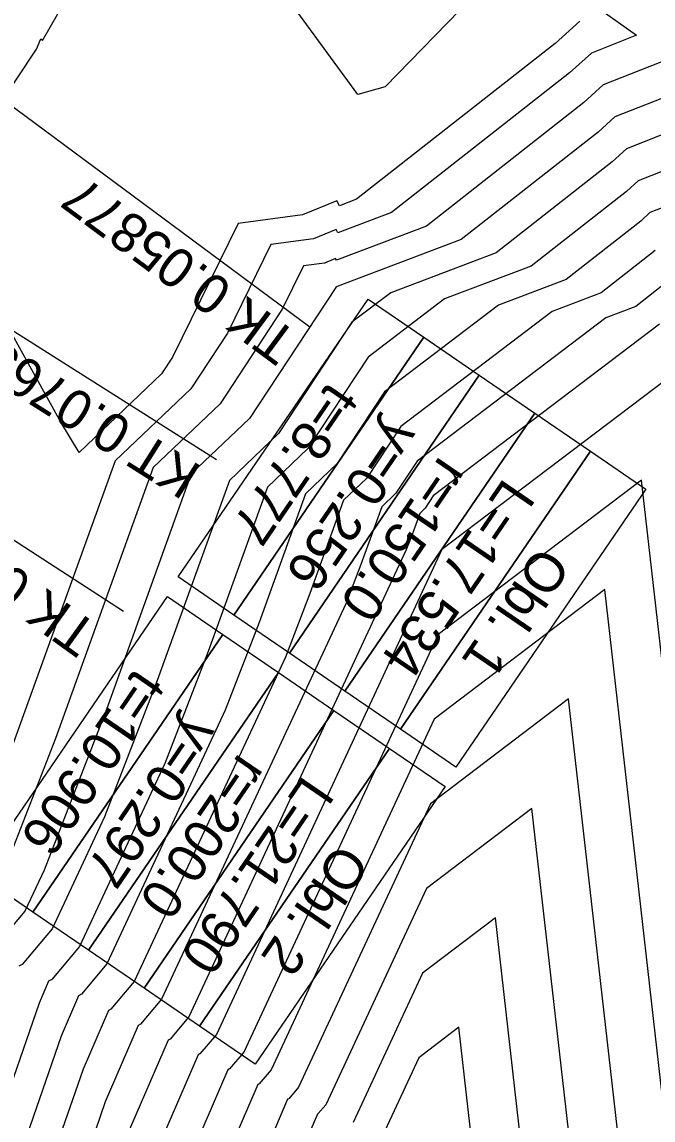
# Model space of a CAD drawing. Extents: x -549394 to -546608, y -1037055 to -1033629.
# Drawn here: x -547683.6 to -547627.3, y -1035531 to -1035433.2 of the extents above; entities that cross this region are included whole.
import ezdxf

# ---------------------------------------------------------------- set-up
doc = ezdxf.new("R2010")
doc.units = 0
for name, color, linetype in [('hlavni_vrst', 7, 'Continuous'), ('norm_vrst', 7, 'Continuous'), ('x_popis_oblouky_C11', 7, 'Continuous')]:
    doc.layers.add(name, color=color, linetype=linetype)

msp = doc.modelspace()

# ---------------------------------------------------------------- linework, layer by layer
at = {"layer": 'hlavni_vrst'}
for p, q in [((-547681.724, -1035434.805), (-547680.351, -1035432.432)), ((-547633.807, -1035433.081), (-547635.991, -1035435.065)), ((-547682.267, -1035435.588), (-547681.864, -1035434.669)), ((-547681.864, -1035434.669), (-547681.724, -1035434.805)), ((-547689.504, -1035446.371), (-547682.267, -1035435.588)), ((-547635.991, -1035435.065), (-547653.716, -1035448.961)), ((-547609.481, -1035439.742), (-547628.59, -1035447.31)), ((-547628.59, -1035447.31), (-547629.638, -1035448.262)), ((-547629.638, -1035448.262), (-547638.141, -1035454.928)), ((-547655.485, -1035449.097), (-547658.547, -1035450.343)), ((-547655.242, -1035449.539), (-547655.485, -1035449.097)), ((-547653.716, -1035448.961), (-547655.242, -1035449.539)), ((-547658.547, -1035450.343), (-547664.284, -1035451.115)), ((-547664.284, -1035451.115), (-547670.133, -1035463.032)), ((-547680.08, -1035468.83), (-547689.44, -1035452.019)), ((-547638.141, -1035454.928), (-547645.859, -1035457.851)), ((-547645.859, -1035457.851), (-547652.671, -1035463.026)), ((-547670.133, -1035463.032), (-547671.116, -1035464.522)), ((-547652.671, -1035463.026), (-547658.046, -1035471.179)), ((-547671.116, -1035464.522), (-547678.465, -1035471.524)), ((-547625.05, -1035464.235), (-547646.101, -1035480.198)), ((-547678.465, -1035471.524), (-547680.08, -1035468.83)), ((-547658.046, -1035471.179), (-547661.662, -1035474.623)), ((-547661.662, -1035474.623), (-547666.946, -1035489.268)), ((-547646.101, -1035480.198), (-547666.218, -1035523.415)), ((-547666.946, -1035489.268), (-547670.822, -1035499.262)), ((-547670.822, -1035499.262), (-547678.409, -1035515.562)), ((-547641.329, -1035513.014), (-547647.822, -1035517.938)), ((-547638.603, -1035537.022), (-547641.329, -1035513.014)), ((-547678.409, -1035515.562), (-547680.899, -1035518.502)), ((-547647.822, -1035517.938), (-547654.027, -1035531.268)), ((-547681.173, -1035518.651), (-547682.031, -1035520.636)), ((-547680.899, -1035518.502), (-547681.173, -1035518.651)), ((-547682.031, -1035520.636), (-547685.776, -1035531.456)), ((-547666.218, -1035523.415), (-547667.69, -1035525.153)), ((-547667.852, -1035525.241), (-547672.195, -1035535.297)), ((-547667.69, -1035525.153), (-547667.852, -1035525.241))]:
    msp.add_line(p, q, dxfattribs=at)
at = {"layer": 'norm_vrst'}
for p, q in [((-547653.591, -1035439.61), (-547662.004, -1035428.111)), ((-547641.292, -1035428.807), (-547651.172, -1035438.937)), ((-547632.01, -1035432.002), (-547628.761, -1035434.341)), ((-547628.761, -1035434.341), (-547632.764, -1035435.927)), ((-547623.941, -1035435.692), (-547631.721, -1035438.773)), ((-547632.764, -1035435.927), (-547634.72, -1035437.704)), ((-547634.72, -1035437.704), (-547650.601, -1035450.154)), ((-547619.121, -1035437.042), (-547630.677, -1035441.619)), ((-547614.301, -1035438.392), (-547629.634, -1035444.464)), ((-547651.172, -1035438.937), (-547653.591, -1035439.61)), ((-547631.721, -1035438.773), (-547633.45, -1035440.344)), ((-547633.45, -1035440.344), (-547647.486, -1035451.348)), ((-547630.677, -1035441.619), (-547632.179, -1035442.983)), ((-547604.661, -1035441.092), (-547627.547, -1035450.156)), ((-547632.179, -1035442.983), (-547644.371, -1035452.541)), ((-547629.634, -1035444.464), (-547630.908, -1035445.623)), ((-547630.908, -1035445.623), (-547641.256, -1035453.735)), ((-547650.601, -1035450.154), (-547655.373, -1035451.961)), ((-547627.547, -1035450.156), (-547628.367, -1035450.902)), ((-547647.486, -1035451.348), (-547655.504, -1035454.384)), ((-547628.367, -1035450.902), (-547635.025, -1035456.122)), ((-547655.534, -1035451.669), (-547657.562, -1035452.494)), ((-547655.373, -1035451.961), (-547655.534, -1035451.669)), ((-547661.36, -1035453.005), (-547665.233, -1035460.896)), ((-547657.562, -1035452.494), (-547661.36, -1035453.005)), ((-547644.371, -1035452.541), (-547655.438, -1035456.732)), ((-547655.583, -1035454.241), (-547656.576, -1035454.645)), ((-547655.504, -1035454.384), (-547655.583, -1035454.241)), ((-547641.256, -1035453.735), (-547650.649, -1035457.292)), ((-547627.096, -1035453.541), (-547631.91, -1035457.315)), ((-547658.437, -1035454.895), (-547660.334, -1035458.76)), ((-547656.576, -1035454.645), (-547658.437, -1035454.895)), ((-547635.025, -1035456.122), (-547641.07, -1035458.411)), ((-547625.826, -1035456.18), (-547628.795, -1035458.509)), ((-547655.572, -1035456.834), (-547663.274, -1035468.517)), ((-547655.438, -1035456.732), (-547655.572, -1035456.834)), ((-547650.649, -1035457.292), (-547654.122, -1035459.93)), ((-547631.91, -1035457.315), (-547636.281, -1035458.97)), ((-547660.334, -1035458.76), (-547665.888, -1035467.185)), ((-547641.07, -1035458.411), (-547651.221, -1035466.122)), ((-547636.281, -1035458.97), (-547649.77, -1035469.218)), ((-547628.795, -1035458.509), (-547631.491, -1035459.529)), ((-547654.122, -1035459.93), (-547660.66, -1035469.848)), ((-547631.491, -1035459.529), (-547648.32, -1035472.314)), ((-547626.702, -1035460.089), (-547646.869, -1035475.41)), ((-547665.233, -1035460.896), (-547668.502, -1035465.854)), ((-547668.502, -1035465.854), (-547675.248, -1035472.28)), ((-547651.221, -1035466.122), (-547655.432, -1035472.511)), ((-547665.888, -1035467.185), (-547671.851, -1035472.866)), ((-547663.274, -1035468.517), (-547668.455, -1035473.452)), ((-547660.66, -1035469.848), (-547665.058, -1035474.038)), ((-547649.77, -1035469.218), (-547652.818, -1035473.842)), ((-547675.248, -1035472.28), (-547685.108, -1035499.605)), ((-547671.851, -1035472.866), (-547680.568, -1035497.021)), ((-547655.432, -1035472.511), (-547658.265, -1035475.209)), ((-547648.32, -1035472.314), (-547650.205, -1035475.173)), ((-547668.455, -1035473.452), (-547676.027, -1035494.437)), ((-547652.818, -1035473.842), (-547654.869, -1035475.795)), ((-547665.058, -1035474.038), (-547671.487, -1035491.853)), ((-547628.306, -1035473.991), (-547646.445, -1035487.746)), ((-547620.69, -1035541.062), (-547628.306, -1035473.991)), ((-547658.265, -1035475.209), (-547662.406, -1035486.684)), ((-547654.869, -1035475.795), (-547657.866, -1035484.1)), ((-547650.205, -1035475.173), (-547651.472, -1035476.381)), ((-547646.869, -1035475.41), (-547647.591, -1035476.505)), ((-547651.472, -1035476.381), (-547653.325, -1035481.516)), ((-547647.591, -1035476.505), (-547648.076, -1035476.967)), ((-547648.076, -1035476.967), (-547648.785, -1035478.932)), ((-547648.785, -1035478.932), (-547649.305, -1035480.273)), ((-547649.305, -1035480.273), (-547668.657, -1035521.844)), ((-547653.325, -1035481.516), (-547654.684, -1035485.021)), ((-547657.866, -1035484.1), (-547660.063, -1035489.768)), ((-547631.562, -1035483.747), (-547646.789, -1035495.294)), ((-547625.168, -1035540.052), (-547631.562, -1035483.747)), ((-547654.684, -1035485.021), (-547671.095, -1035520.274)), ((-547662.406, -1035486.684), (-547665.443, -1035494.515)), ((-547646.445, -1035487.746), (-547663.78, -1035524.985)), ((-547660.063, -1035489.768), (-547673.533, -1035518.703)), ((-547671.487, -1035491.853), (-547676.201, -1035504.009)), ((-547634.818, -1035493.503), (-547647.134, -1035502.842)), ((-547629.646, -1035539.042), (-547634.818, -1035493.503)), ((-547676.027, -1035494.437), (-547681.58, -1035508.757)), ((-547665.443, -1035494.515), (-547675.971, -1035517.133)), ((-547646.789, -1035495.294), (-547661.342, -1035526.556)), ((-547680.568, -1035497.021), (-547685.132, -1035508.792)), ((-547647.134, -1035502.842), (-547658.904, -1035528.127)), ((-547638.073, -1035503.258), (-547647.478, -1035510.39)), ((-547634.125, -1035538.032), (-547638.073, -1035503.258)), ((-547676.201, -1035504.009), (-547680.848, -1035513.991)), ((-547681.58, -1035508.757), (-547683.286, -1035512.421)), ((-547647.478, -1035510.39), (-547656.465, -1035529.697)), ((-547683.286, -1035512.421), (-547684.545, -1035513.908)), ((-547680.848, -1035513.991), (-547683.541, -1035517.172)), ((-547683.541, -1035517.172), (-547683.837, -1035517.333)), ((-547675.971, -1035517.133), (-547678.257, -1035519.833)), ((-547673.533, -1035518.703), (-547675.616, -1035521.163)), ((-547678.257, -1035519.833), (-547678.509, -1035519.969)), ((-547678.509, -1035519.969), (-547680.064, -1035523.569)), ((-547671.095, -1035520.274), (-547672.974, -1035522.493)), ((-547675.845, -1035521.287), (-547678.097, -1035526.501)), ((-547675.616, -1035521.163), (-547675.845, -1035521.287)), ((-547668.657, -1035521.844), (-547670.332, -1035523.823)), ((-547673.18, -1035522.605), (-547676.129, -1035529.433)), ((-547672.974, -1035522.493), (-547673.18, -1035522.605)), ((-547644.585, -1035522.77), (-547648.167, -1035525.486)), ((-547643.082, -1035536.012), (-547644.585, -1035522.77)), ((-547680.064, -1035523.569), (-547683.396, -1035533.197)), ((-547670.332, -1035523.823), (-547670.516, -1035523.923)), ((-547670.516, -1035523.923), (-547674.162, -1035532.365)), ((-547663.78, -1035524.985), (-547665.048, -1035526.483)), ((-547648.167, -1035525.486), (-547651.589, -1035532.838)), ((-547678.097, -1035526.501), (-547681.017, -1035534.937)), ((-547665.188, -1035526.559), (-547670.228, -1035538.229)), ((-547665.048, -1035526.483), (-547665.188, -1035526.559)), ((-547661.342, -1035526.556), (-547662.407, -1035527.813)), ((-547662.524, -1035527.877), (-547668.261, -1035541.161)), ((-547662.407, -1035527.813), (-547662.524, -1035527.877)), ((-547658.904, -1035528.127), (-547659.765, -1035529.144)), ((-547676.129, -1035529.433), (-547678.637, -1035536.678)), ((-547659.86, -1035529.195), (-547666.294, -1035544.093)), ((-547659.765, -1035529.144), (-547659.86, -1035529.195)), ((-547656.465, -1035529.697), (-547657.123, -1035530.474)), ((-547657.195, -1035530.513), (-547664.327, -1035547.025)), ((-547657.123, -1035530.474), (-547657.195, -1035530.513))]:
    msp.add_line(p, q, dxfattribs=at)
at = {"layer": 'x_popis_oblouky_C11'}
for points in [[(-547657.886, -1035460.352), (-547691.135, -1035435.731)], [(-547666.193, -1035472.192), (-547701.172, -1035450.096)], [(-547709.226, -1035463.191), (-547674.501, -1035485.684)]]:
    msp.add_lwpolyline(points, dxfattribs=at)
for points in [[(-547647.719, -1035461.263), (-547664.659, -1035486.023), (-547669.611, -1035482.634), (-547652.671, -1035457.875)], [(-547642.767, -1035464.651), (-547659.707, -1035489.411), (-547664.659, -1035486.023), (-547647.719, -1035461.263)], [(-547637.815, -1035468.04), (-547654.756, -1035492.799), (-547659.707, -1035489.411), (-547642.767, -1035464.651)], [(-547632.863, -1035471.428), (-547649.804, -1035496.187), (-547654.756, -1035492.799), (-547637.815, -1035468.04)], [(-547627.911, -1035474.816), (-547644.852, -1035499.575), (-547649.804, -1035496.187), (-547632.863, -1035471.428)], [(-547665.63, -1035487.755), (-547682.57, -1035512.514), (-547687.522, -1035509.126), (-547670.582, -1035484.367)], [(-547660.678, -1035491.143), (-547677.619, -1035515.902), (-547682.57, -1035512.514), (-547665.63, -1035487.755)], [(-547655.726, -1035494.531), (-547672.667, -1035519.29), (-547677.619, -1035515.902), (-547660.678, -1035491.143)], [(-547650.774, -1035497.919), (-547667.715, -1035522.678), (-547672.667, -1035519.29), (-547655.726, -1035494.531)], [(-547645.823, -1035501.307), (-547662.763, -1035526.066), (-547667.715, -1035522.678), (-547650.774, -1035497.919)]]:
    msp.add_lwpolyline(points, close=True, dxfattribs=at)

# ---------------------------------------------------------------- texts
for s, rotation, p in [('TK 0.05877', 143.47953, (-547658.753, -1035461.076)), ('KT 0.07631', 147.7195, (-547667.382, -1035472.875)), ('t=8.777', 235.64153, (-547656.167, -1035465.121)), ('y=0.256', 235.64153, (-547650.661, -1035468.323)), ('r=150.0', 235.64153, (-547646.272, -1035471.751)), ('TK 0.09168', 144.25718, (-547676.569, -1035487.068)), ('L=17.534', 235.64153, (-547640.54, -1035473.695)), ('Obl. 1', 235.64153, (-547637.397, -1035479.729)), ('t=10.906', 235.64153, (-547673.42, -1035490.651)), ('y=0.297', 235.64153, (-547668.572, -1035494.814)), ('r=200.0', 235.64153, (-547664.183, -1035498.243)), ('L=21.790', 235.64153, (-547658.451, -1035500.186)), ('Obl. 2', 235.64153, (-547655.308, -1035506.221))]:
    msp.add_text(s, height=3.5, rotation=rotation, dxfattribs=at).set_placement(p)

doc.saveas('drawing.dxf')
